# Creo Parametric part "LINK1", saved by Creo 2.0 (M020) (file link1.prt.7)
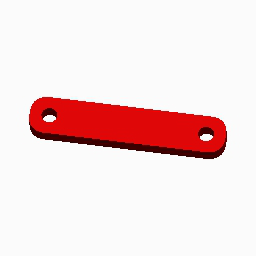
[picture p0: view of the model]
Units: Inch lbm Second (Pro/E Default); INCH, POUND, SECS

Created from: INLBS_PART_SOLID.PRT

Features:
  1. datum plane "RIGHT"
  2. datum plane "TOP"
  3. datum plane "FRONT"
  4. coordinate system
  5. sketch "Sketch 1"
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
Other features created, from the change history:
  datum plane "DTM1"
  extrusion "Extrude 1"
  datum plane "BOTTON"
  round "Round 1"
